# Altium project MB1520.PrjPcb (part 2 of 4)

## Sheet Arduino_Connector.SchDoc: Arduino Connector
size A4; Date: Not used; ApprovedBy: Not used; CheckedBy: Not used; Author: Not used; CompanyName: STMicroelectronics; DrawnBy: Not used; Engineer: Not used; Organization: Not used; Address1: Not used; Address2: Not used; Address3: Not used; Address4: Not used; DocumentNumber: Not used; Revision: Not used; SheetNumber: 16; SheetTotal: 19
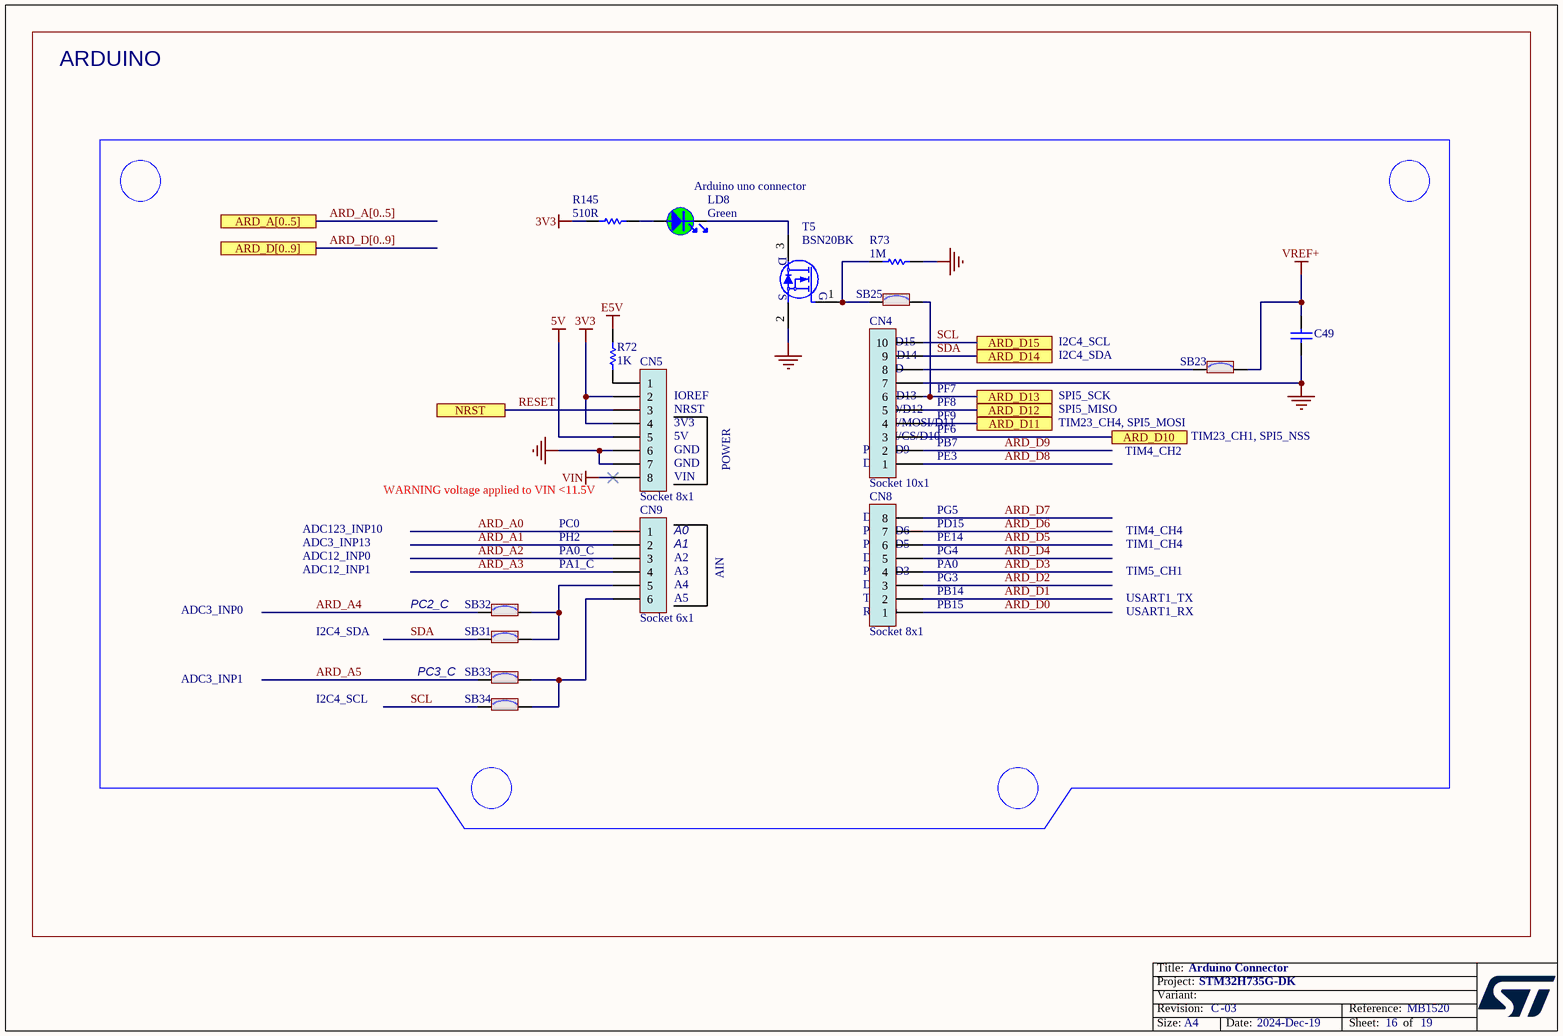
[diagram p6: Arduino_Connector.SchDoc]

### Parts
C49  Capacitor  [C0603]  (value not drawn)
CN4  Socket 10x1  [CON_SAMTEC_SSW-110-22-X-S-VS]
CN5  Socket 8x1  [CON_SAMTEC_SSW-108-22-X-S-VS]
CN8  Socket 8x1  [CON_SAMTEC_SSW-108-22-X-S-VS]
CN9  Socket 6x1  [CON_SAMTEC_SSW-106-22-X-S-VS]
LD8  value Green  [LED_0603_GREEN]  (hidden comment: LED_green)
R72  value 1K  [R0603]  (hidden comment: Resistor)
R73  value 1M  [R0603]  (hidden comment: Resistor)
R145  value 510R  [R0603]  (hidden comment: Resistor)
SB23  SB_ON  [SOLDER-BRIDGE_R0603-0R]  (value not drawn)
SB25  SB_ON  [SOLDER-BRIDGE_R0603-0R]  (value not drawn)
SB31  SB_ON  [SOLDER-BRIDGE_R0603-0R]  (value not drawn)
SB32  SB_ON  [SOLDER-BRIDGE_R0603-0R]  (value not drawn)
SB33  SB_ON  [SOLDER-BRIDGE_R0603-0R]  (value not drawn)
SB34  SB_ON  [SOLDER-BRIDGE_R0603-0R]  (value not drawn)
T5  value BSN20BK  [MOS_SOT23]  (hidden comment: BSN20)

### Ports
ARD_A[0..5], ARD_D10, ARD_D11, ARD_D12, ARD_D13, ARD_D14, ARD_D15, ARD_D[0..9], NRST

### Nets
3V3: CN5.2 CN5.4 R145.2
5V: CN5.5
E5V: R72.1
GND: C49.1 CN4.7 CN5.6 CN5.7 R73.2 T5.2(S)  [project net POE7]
VIN: CN5.8
VREF+: C49.2 SB23.2
ARD_A0: CN9.1
ARD_A1: CN9.2
ARD_A2: CN9.3
ARD_A3: CN9.4
ARD_A4: SB32.1
ARD_A5: SB33.1
ARD_D0: CN8.1
ARD_D1: CN8.2
ARD_D2: CN8.3
ARD_D3: CN8.4
ARD_D4: CN8.5
ARD_D5: CN8.6
ARD_D6: CN8.7
ARD_D7: CN8.8
ARD_D8: CN4.1
ARD_D9: CN4.2
ARD_D10: CN4.3 ; port ARD_D10
ARD_D11: CN4.4 ; port ARD_D11
ARD_D12: CN4.5 ; port ARD_D12
ARD_D13: CN4.6 SB25.2 ; port ARD_D13
RESET: CN5.3 ; port NRST
SCL: CN4.10 SB34.1 ; port ARD_D15
SDA: CN4.9 SB31.1 ; port ARD_D14
NetCN4_8: CN4.8 SB23.1
NetCN5_1: CN5.1 R72.2
NetCN9_5: CN9.5 SB31.2 SB32.2
NetCN9_6: CN9.6 SB33.2 SB34.2
NetLD8_1: LD8.1 R145.1
NetLD8_2: LD8.2 T5.3(D)
NetR73_1: R73.1 SB25.1 T5.1(G)

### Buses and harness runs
bus ARD_A[0..5] = port ARD_A[0..5]
bus ARD_D[0..9] = port ARD_D[0..9]

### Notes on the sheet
- ARDUINO
- (near LD8) Arduino uno connector
- (near CN4) SDA/D14
- SCL/D15
- (near CN4) AVDD
- (near CN4) GND
- I2C4_SCL
- I2C4_SDA
- (near CN5) IOREF
- (near CN5) NRST
- (near CN5) 3V3
- (near CN5) 5V
- (near CN4) PWM/CS/D10
- (near CN4) SCK/D13
- (near CN4) MISO/D12
- (near CN4) PWM/MOSI/D11
- (near CN4) PF6
- (near CN4) PB7
- (near CN4) PF9
- (near CN4) PF8
- (near CN4) PF7
- TIM23_CH4, SPI5_MOSI
- SPI5_MISO
- SPI5_SCK
- TIM23_CH1, SPI5_NSS
- WARNING voltage applied to VIN <11.5V
- (near CN5) GND
- (near CN5) VIN
- POWER
- (near CN8) D7
- (near CN4) D8
- (near CN4) PWM/D9
- PG5
- (near CN4) PE3
- TIM4_CH2
- ADC12_INP1
- ADC12_INP0
- ADC3_INP13
- ADC123_INP10
- PC0
- PH2
- PA0_C
- PA1_C
- (near CN9) A0
- (near CN9) A1
- (near CN9) A2
- (near CN9) A3
- AIN
- (near CN8) D4
- (near CN8) PWM/D3
- (near CN8) PWM/D5
- (near CN8) PWM/D6
- (near CN8) PG3
- (near CN8) PG4
- (near CN8) PE14
- (near CN8) PD15
- (near CN8) PA0
- TIM1_CH4
- TIM5_CH1
- TIM4_CH4
- ADC3_INP0
- PC2_C
- (near CN9) A4
- (near CN9) A5
- (near CN8) RX/D0
- (near CN8) TX/D1
- (near CN8) D2
- (near CN8) PB14
- (near CN8) PB15
- USART1_RX
- USART1_TX
- ADC3_INP1
- PC3_C

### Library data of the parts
C49 = MCD-00211: Capacitor, MLCC, 100nF, 16V, X7R, 10%, 0603, T=0,8mm; Manufacturer_Part_Number: CC0603KRX7R7BB104; Manufacturer: YAGEO; Part_Preference: Recommended; Provided_By: SUBCO; Component_Country_Of_Origin: China; ID: 2659; Order_Code_RS: 669-8763; ShowFields: YES
CN4 = MCD-00301: Socket, 10x1, 2.54mm, VR, SMT, Height 9.78mm; Manufacturer_Part_Number: SSW-110-22-L-S-VS; Manufacturer: SAMTEC; Part_Type: Connector; Part_Preference: Recommended; Provided_By: SUBCO; Component_Country_Of_Origin: China, Costa Rica, Malaysia, United States, Vietnam; ID: 2566; ShowFields: YES
CN5 = MCD-00300: Socket, 8x1, 2.54mm, VR, SMT, Height 9.78mm; Manufacturer_Part_Number: SSW-108-22-L-S-VS; Manufacturer: SAMTEC; Part_Type: Connector; Part_Preference: Recommended; Provided_By: SUBCO; Component_Country_Of_Origin: China, Costa Rica, Malaysia, United States, Vietnam; ID: 2571; ShowFields: YES
CN8 = MCD-00300: Socket, 8x1, 2.54mm, VR, SMT, Height 9.78mm; Part_Type: Connector; Manufacturer_Part_Number: SSW-108-22-L-S-VS; Manufacturer: SAMTEC; Part_Preference: Recommended; Provided_By: SUBCO; Component_Country_Of_Origin: China, Costa Rica, Malaysia, United States, Vietnam; ID: 2571; ShowFields: YES
CN9 = MCD-00299: Socket, 6x1, 2.54mm, VR, SMT, Height 9.78mm; Part_Type: Connector; Manufacturer_Part_Number: SSW-106-22-L-S-VS; Manufacturer: SAMTEC; Part_Preference: Recommended; Provided_By: SUBCO; Component_Country_Of_Origin: China, Costa Rica, Malaysia, United States, Vietnam; ID: 2569; ShowFields: YES
LD8 = MCD-02900: LED, Green, 2V, 20mA, 0603; Part_Type: Display; Manufacturer_Part_Number: 19-213SYGC/S530-E2/5T; Manufacturer: EVERLIGHT; Full_Alternate_Internal_Part_Number: MCD-00320; Part_Preference: Recommended; Partial_Alternate_Internal_Part_Number: MCD-00050; Component_Country_Of_Origin: China; ID: 5016; ShowFields: YES
R72 = MCD-00070: Resistor,1K,0603,1%,1/10W; Manufacturer_Part_Number: RC0603FR-071KL; Manufacturer: YAGEO; Part_Preference: Recommended; Provided_By: SUBCO; Component_Country_Of_Origin: China; ID: 2522; ShowFields: YES
R73 = MCD-00257: Resistor,1M,0603,1%,1/10W; Manufacturer_Part_Number: RC0603FR-071ML; Manufacturer: YAGEO; Part_Preference: Recommended; Provided_By: SUBCO; Component_Country_Of_Origin: China; ID: 2612; ShowFields: YES
R145 = MCD-00225: Resistor,510R,0603,1%,1/10W; Manufacturer_Part_Number: RC0603FR-07510RL; Manufacturer: YAGEO; Part_Preference: Recommended; Provided_By: SUBCO; Component_Country_Of_Origin: China; ID: 2644; ShowFields: YES
SB23 SB25 SB31-SB34 = MCD-00071: Solder Bridge ON; Part_Type: Misc; Manufacturer_Part_Number: RC0603JR-070RL; Manufacturer: YAGEO; Part_Preference: Recommended; Provided_By: SUBCO; ID: 2521; ShowFields: YES
T5 = MCD-01969: Transistor, N-channel enhancement mode field-effect transistor; Manufacturer: NEXPERIA; Part_Preference: Recommended; ID: 4069; Order_Code_RS: 136-4845; ShowFields: YES; Component_Country_Of_Origin: China

## Sheet STMod+.SchDoc: STMod+
size A4; Date: Not used; ApprovedBy: Not used; CheckedBy: Not used; Author: Not used; CompanyName: STMicroelectronics; DrawnBy: Not used; Engineer: Not used; Organization: Not used; Address1: Not used; Address2: Not used; Address3: Not used; Address4: Not used; DocumentNumber: Not used; Revision: Not used; SheetNumber: 14; SheetTotal: 19
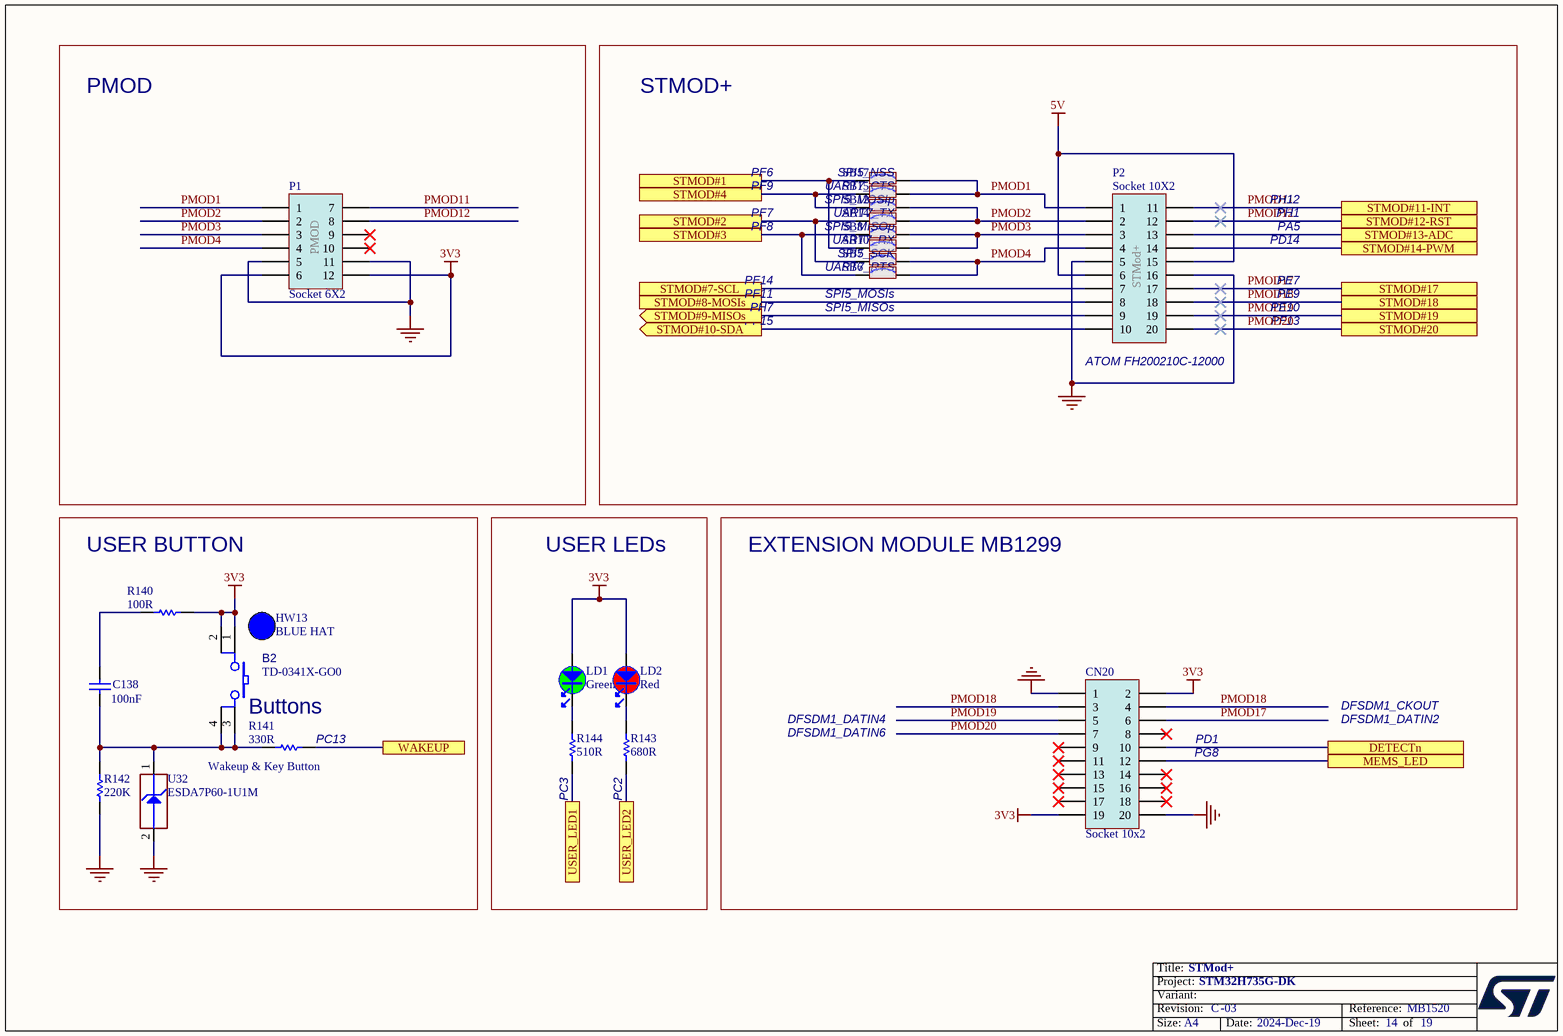
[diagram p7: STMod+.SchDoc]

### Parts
B2  Manufacturer_Part_Number: TD-0341X-GO0  [SWI_WEALTHMETAL_TD-0341_4P_BLUE]  (hidden comment: SW-PUSH-CMS)
C138  value 100nF  [C0402]  (hidden comment: Capacitor)
CN20  Socket 10x2  [CON_FCI_20021311-XXX20XXLF]
HW13  value BLUE HAT  (hidden comment: BUTTON_HAT_BLUE)  (mechanical)
LD1  value Green  [LED_0603_GREEN]  (hidden comment: LED_green)
LD2  value Red  [LED_0603_RED]  (hidden comment: LED_red)
P1  value Socket 6X2  [CON_SAMTEC_SSW-106-02-F-D-RA__PMOD]  (hidden comment: Socket 6X2 PMOD)
P2  value Socket 10X2  [CON_SAMTEC_SQT-110-01-F-D-RA__STMOD+]  (hidden comment: Socket 10X2 STMod+)
R140  value 100R  [R0402]  (hidden comment: Resistor)
R141  value 330R  [R0402]  (hidden comment: Resistor)
R142  value 220K  [R0402]  (hidden comment: Resistor)
R143  value 680R  [R0603]  (hidden comment: Resistor)
R144  value 510R  [R0603]  (hidden comment: Resistor)
SB6  SB_ON  [SOLDER-BRIDGE_R0603-0R]  (value not drawn)
SB7  SB_ON  [SOLDER-BRIDGE_R0603-0R]  (value not drawn)
SB8  SB_ON  [SOLDER-BRIDGE_R0603-0R]  (value not drawn)
SB10  SB_ON  [SOLDER-BRIDGE_R0603-0R]  (value not drawn)
SB12  SB_ON  [SOLDER-BRIDGE_R0603-0R]  (value not drawn)
SB14  SB_ON  [SOLDER-BRIDGE_R0603-0R]  (value not drawn)
SB15  SB_ON  [SOLDER-BRIDGE_R0603-0R]  (value not drawn)
SB17  SB_ON  [SOLDER-BRIDGE_R0603-0R]  (value not drawn)
U32  value ESDA7P60-1U1M  [ESD_QFN2_1P6X1_P125]  (hidden comment: ESD-TRANSIL)

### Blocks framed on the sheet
PMOD: P1
STMOD+: P2 SB6-SB8 SB10 SB12 SB14 SB15 SB17
USER LEDs: LD1 LD2 R143 R144
EXTENSION MODULE MB1299: CN20

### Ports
DETECTn, MEMS_LED, STMOD#1, STMOD#2, STMOD#3, STMOD#4, STMOD#7-SCL, STMOD#8-MOSIs, STMOD#9-MISOs (out), STMOD#10-SDA (out), STMOD#11-INT, STMOD#12-RST, STMOD#13-ADC, STMOD#14-PWM, STMOD#17, STMOD#18, STMOD#19, STMOD#20, USER_LED1, USER_LED2, WAKEUP

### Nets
3V3: B2.1 B2.2 CN20.2 CN20.19 LD1.1 LD2.1 P1.6 P1.12 R140.2
5V: P2.6 P2.15
GND: CN20.1 CN20.20 P1.5 P1.11 P2.5 P2.16 R142.1 U32.2(GND)  [project net POE7]
DETECTn: CN20.10 ; port DETECTn
MEMS_LED: CN20.12 ; port MEMS_LED
PF6: SB10.1 SB17.1 ; port STMOD#1
PF7: SB7.1 SB14.1 ; port STMOD#2
PMOD1: P1.1 P2.1 SB15.2 SB17.2
PMOD2: P1.2 P2.2 SB12.2 SB14.2
PMOD3: P1.3 P2.3 SB8.2 SB10.2
PMOD4: P1.4 P2.4 SB6.2 SB7.2
PMOD11: P1.7 P2.11 ; port STMOD#11-INT
PMOD12: P1.8 P2.12 ; port STMOD#12-RST
PMOD17: CN20.6 P2.17 ; port STMOD#17
PMOD18: CN20.3 CN20.4 P2.18 ; port STMOD#18
PMOD19: CN20.5 P2.19 ; port STMOD#19
PMOD20: CN20.7 P2.20 ; port STMOD#20
STMOD#3: SB6.1 SB8.1 ; port STMOD#3
STMOD#4: SB12.1 SB15.1 ; port STMOD#4
STMOD#7-SCL: P2.7 ; port STMOD#7-SCL
STMOD#8-MOSIs: P2.8 ; port STMOD#8-MOSIs
STMOD#9-MISOs: P2.9 ; port STMOD#9-MISOs
STMOD#10-SDA: P2.10 ; port STMOD#10-SDA
STMOD#13-ADC: P2.13 ; port STMOD#13-ADC
STMOD#14-PWM: P2.14 ; port STMOD#14-PWM
USER_LED1: R144.1 ; port USER_LED1
USER_LED2: R143.1 ; port USER_LED2
WAKEUP: R141.2 ; port WAKEUP
NetB2_3: B2.3 B2.4 C138.2 R141.1 R142.2 U32.1(IO1)
NetC138_1: C138.1 R140.1
NetLD1_2: LD1.2 R144.2
NetLD2_2: LD2.2 R143.2

Not connected (* = marked no-connect by the designer): CN20 8* 9* 11* 13* 14* 15* 16* 17* 18*; P1 9* 10*

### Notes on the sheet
- PF6
- (near SB17) SPI5_NSS
- PF9
- PF7
- PF8
- UART7_CTS
- SPI5_MOSIp
- UART7_TX
- SPI5_MISOp
- UART7_RX
- PH1
- PA5
- PH12
- PD14
- PF14
- PF11
- PH7
- SPI5_SCK
- UART7_RTS
- (near SB6) SPI5_MOSIs
- SPI5_MISOs
- PE7
- PE9
- PE10
- PF15
- (near P2) ATOM FH200210C-12000
- PF13
- USER BUTTON
- (near B2) Buttons
- DFSDM1_CKOUT
- (near R141) Wakeup & Key Button
- (near R141) PC13
- DFSDM1_DATIN4
- DFSDM1_DATIN6
- PD1
- PG8
- DFSDM1_DATIN2
- (near R144) PC3
- (near R143) PC2

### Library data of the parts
B2 = MCD-00002: Non-Open Push-Button 0.1A 24V; Part_Type: Misc; Manufacturer: WEALTHMETAL; Part_Preference: Not recommended; Partial_Alternate_Internal_Part_Number: MCD-03589; Value: SWITCH; Provided_By: SUBCO; Alternate_EMS: A; Component_Country_Of_Origin: Unknown; ID: 2464; ShowFields: YES
C138 = MCD-00006: Capacitor, MLCC, 100nF, 16V, X7R, +/-10%, 0402, T=0.5mm; Manufacturer_Part_Number: CC0402KRX7R7BB104; Manufacturer: YAGEO; Part_Preference: Recommended; Partial_Alternate_Internal_Part_Number: MCD-03299; Component_Country_Of_Origin: China; ID: 2474; Order_Code_RS: 616-9701; ShowFields: YES
CN20 = MCD-00147: Socket for MB1299, 10x2, 1.27mm, VR, TH, Height 4.30mm/2.40mm; Part_Type: Connector; Manufacturer_Part_Number: 20021311-00020T4LF; Manufacturer: AMPHENOL ICC; Alternate_Manufacturer_Part_Number: 234220S1410; Alternate_Manufacturer: JIUBABA; Part_Preference: Recommended; Provided_By: SUBCO; Component_Country_Of_Origin: China; ID: 2719; Order_Code_RS: 170-8859; ShowFields: YES
HW13 = MCD-00634: Blue Hat for switch TD0341X-G01-BLU; Part_Type: Misc; Manufacturer_Part_Number: 988.16.09.3.00002_SH-517; Manufacturer: JIUBABA; Part_Preference: Alternate; Provided_By: SUBCO; Alternate_EMS: A; Component_Country_Of_Origin: Unknown; ID: 3112; ShowFields: YES
LD1 = MCD-02900: as LD8 on sheet Arduino_Connector
LD2 = MCD-02899: LED, Red, 2V35, 20mA, 0603; Manufacturer_Part_Number: 19-213/R6C-AP1Q2B/5T; Manufacturer: EVERLIGHT; Part_Type: Display; Full_Alternate_Internal_Part_Number: MCD-00049; Part_Preference: Recommended; Component_Country_Of_Origin: China; ID: 5015; ShowFields: YES
P1 = MCD-00308: Socket, 6x2, 2.54mm, TH, RA, Height 8.51mm/7.62mm; Part_Type: Connector; Manufacturer_Part_Number: SSW-106-02-F-D-RA; Manufacturer: SAMTEC; Part_Preference: Recommended; Provided_By: SUBCO; Component_Country_Of_Origin: China, Costa Rica, Malaysia, United States, Vietnam; ID: 2562; Order_Code_RS: 207-9142; ShowFields: YES
P2 = MCD-00309: Socket 10x2, 2.00mm, RA, TH, Height 6.35mm/2.29mm; Part_Type: Connector; Manufacturer_Part_Number: SQT-110-01-F-D-RA; Manufacturer: SAMTEC; Alternate_Manufacturer_Part_Number: FH200020C-12300; Alternate_Manufacturer: JIUBABA; Part_Preference: Recommended; Provided_By: SUBCO; Component_Country_Of_Origin: China, Costa Rica, Malaysia, United States, Vietnam; ID: 2557; Order_Code_RS: 180-1541; ShowFields: YES
R140 = MCD-00067: Resistor, 100R, 0402, +/- 1%, 1/16W; Manufacturer_Part_Number: RC0402FR-07100RL; Manufacturer: YAGEO; Part_Preference: Recommended; Component_Country_Of_Origin: China; ID: 2527; ShowFields: YES
R141 = MCD-00062: Resistor,330R,0402,1%,1/16W; Manufacturer_Part_Number: RC0402FR-07330RL; Manufacturer: YAGEO; Part_Preference: Recommended; Provided_By: SUBCO; Component_Country_Of_Origin: China; ID: 2529; ShowFields: YES
R142 = MCD-00164: Resistor,220K,0402,1%,1/16W; Manufacturer_Part_Number: RC0402FR-07220KL; Manufacturer: YAGEO; Part_Preference: Recommended; Provided_By: SUBCO; Component_Country_Of_Origin: China; ID: 2704; ShowFields: YES
R143 = MCD-00508: Resistor,680R,0603,1%,1/10W; Manufacturer_Part_Number: RC0603FR-07680RL; Manufacturer: YAGEO; Part_Preference: Recommended; ECCN_US: EAR99; ECCN_EU: NEC; Provided_By: SUBCO; Component_Country_Of_Origin: China; ID: 3235; ShowFields: YES
R144 = MCD-00225: as R145 on sheet Arduino_Connector
SB6-SB8 SB10 SB12 SB14 SB15 SB17 = MCD-00071: as SB23 on sheet Arduino_Connector
U32 = MCD-00251: High power transient voltage suppressor, 7V breakdown; Part_Type: Diode; Manufacturer: STMICROELECTRONICS; BMS_Part_Number: 9179042; Manufacturer_HQ_COO: EU; Part_Preference: Recommended; Provided_By: SUBCO with ST control; Component_Country_Of_Origin: China; ID: 2618; ShowFields: YES

## Sheet STM32_microcontroller_IOs.SchDoc: STM32 microcontroller IOs
size A3; Date: Not used; ApprovedBy: Not used; CheckedBy: Not used; Author: Not used; CompanyName: STMicroelectronics; DrawnBy: Not used; Engineer: Not used; Organization: Not used; Address1: Not used; Address2: Not used; Address3: Not used; Address4: Not used; DocumentNumber: Not used; Revision: Not used; SheetNumber: 3; SheetTotal: 19
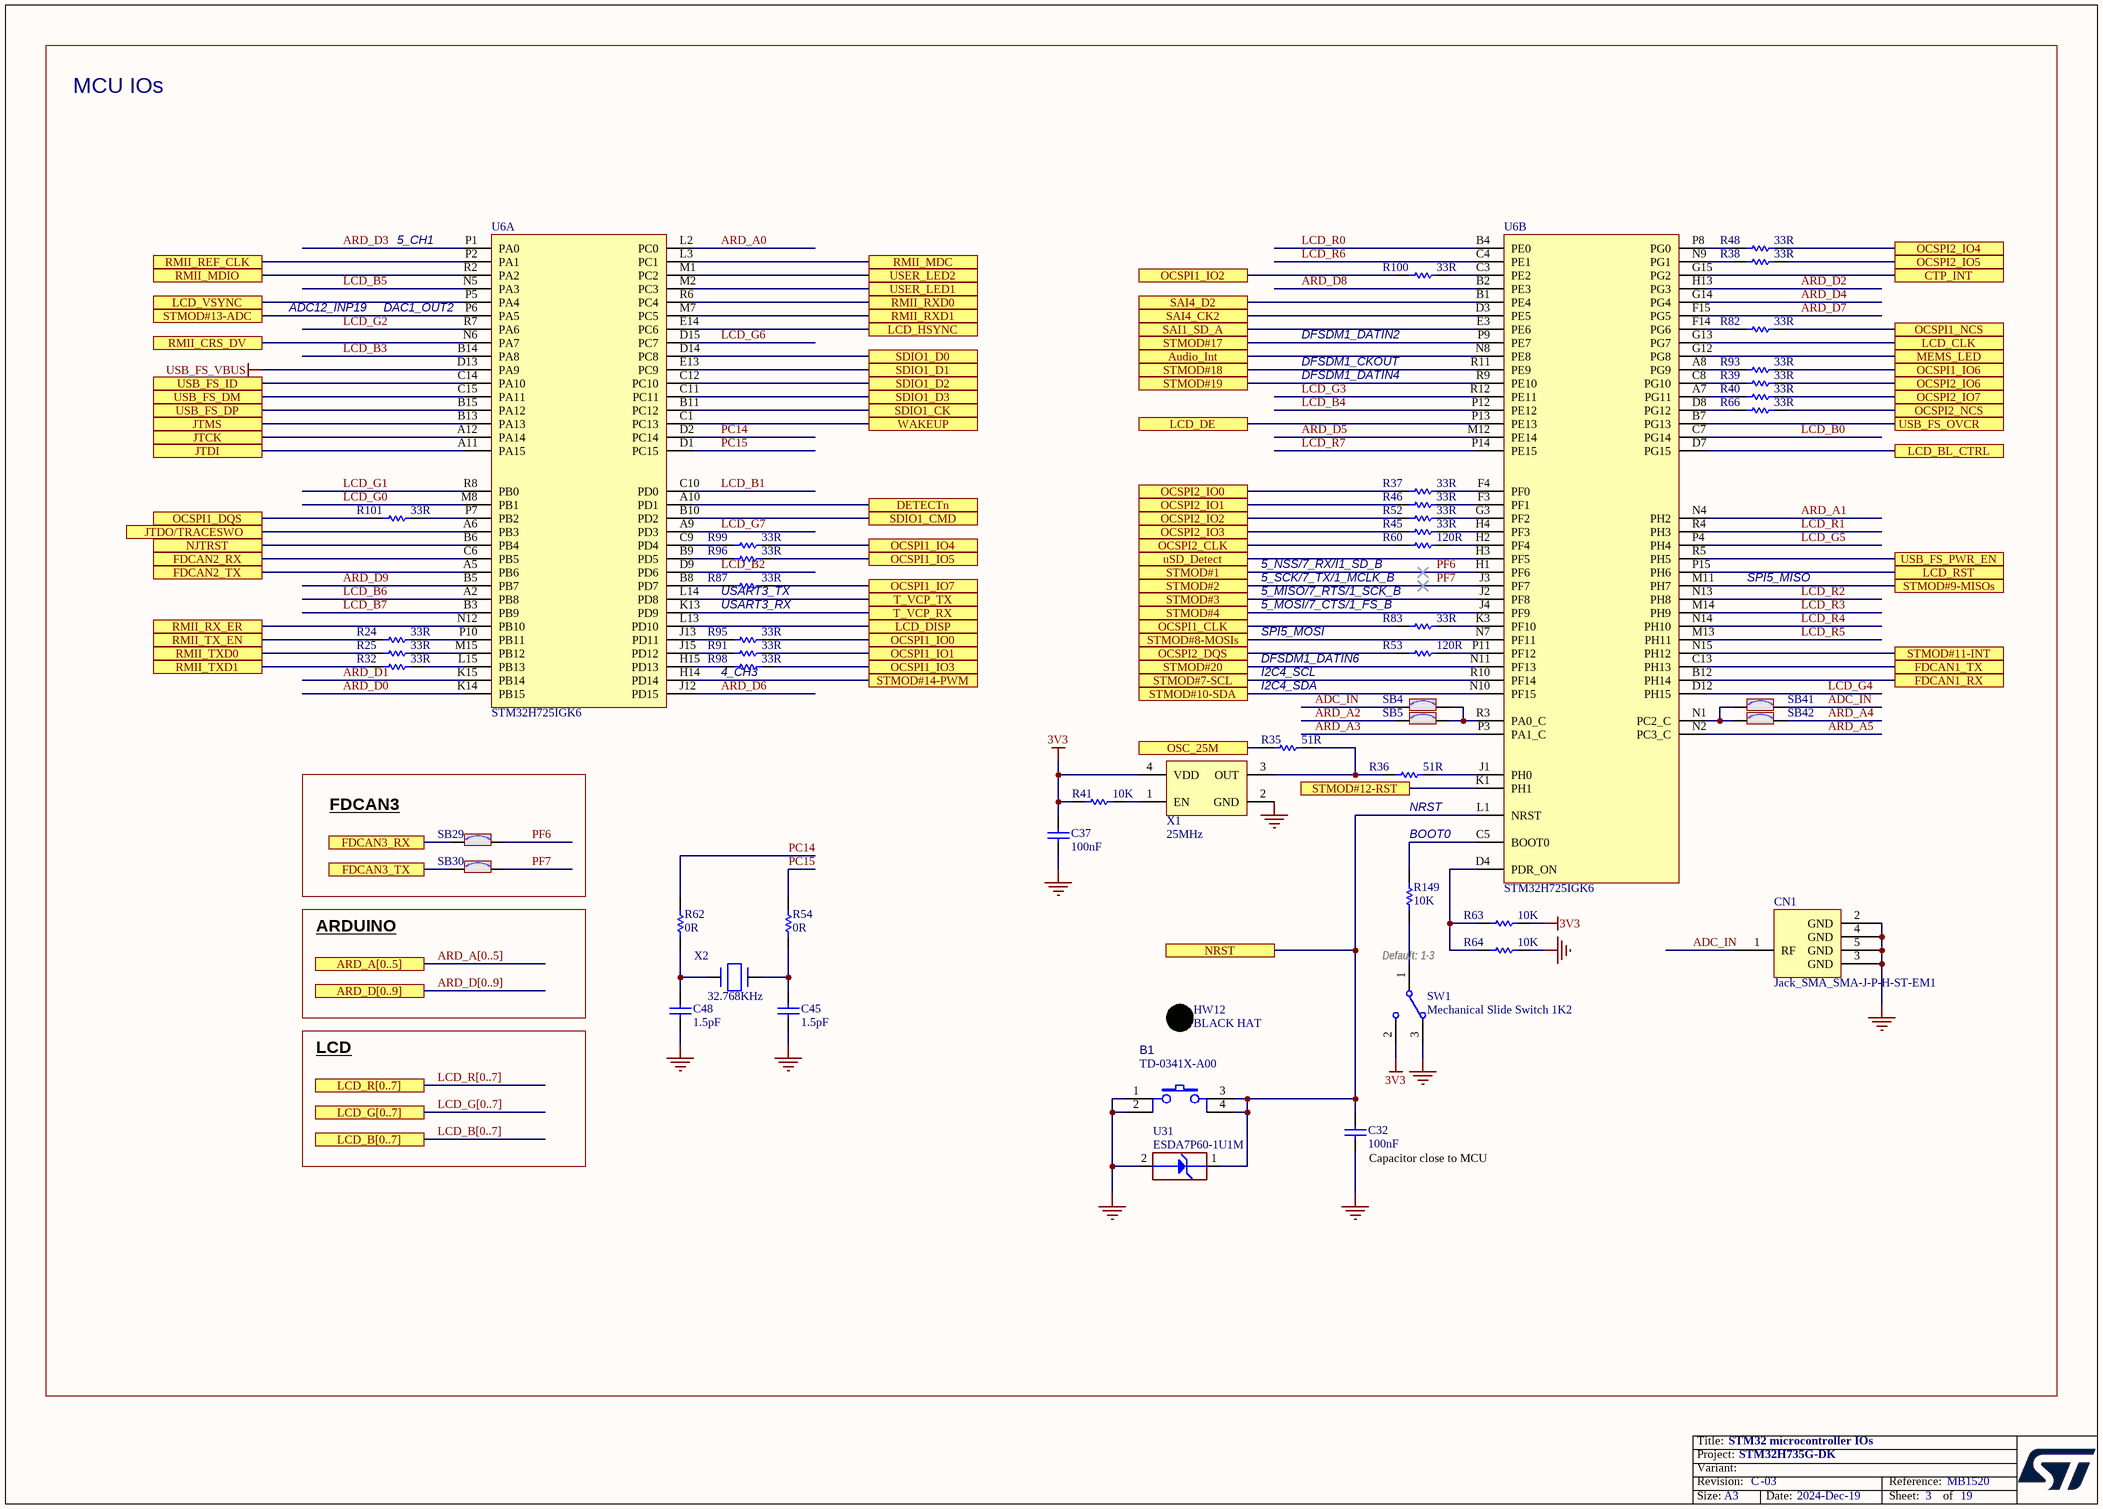
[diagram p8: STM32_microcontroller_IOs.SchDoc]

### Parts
B1  Manufacturer_Part_Number: TD-0341X-A00  [SWI_WEALTHMETAL_TD-0341_4P_BLACK]  (hidden comment: SW-PUSH-CMS)
C32  value 100nF  [C0402]  (hidden comment: Capacitor)
C37  value 100nF  [C0402]  (hidden comment: Capacitor)
C45  value 1.5pF  [C0402]  (hidden comment: Capacitor)
C48  value 1.5pF  [C0402]  (hidden comment: Capacitor)
CN1  value Jack_SMA_SMA-J-P-H-ST-EM1  [CON_SAMTEC_SMA-J-P-X-ST-EM1]  (hidden comment: SMA-J-P-H-ST-EM1)
HW12  value BLACK HAT  (hidden comment: BUTTON_HAT_BLACK)  (mechanical)
R24  value 33R  [R0402]  (hidden comment: Resistor)
R25  value 33R  [R0402]  (hidden comment: Resistor)
R32  value 33R  [R0402]  (hidden comment: Resistor)
R35  value 51R  [R0402]  (hidden comment: Resistor)
R36  value 51R  [R0402]  (hidden comment: Resistor)
R37  value 33R  [R0402]  (hidden comment: Resistor)
R38  value 33R  [R0402]  (hidden comment: Resistor)
R39  value 33R  [R0402]  (hidden comment: Resistor)
R40  value 33R  [R0402]  (hidden comment: Resistor)
R41  value 10K  [R0402]  (hidden comment: Resistor)
R45  value 33R  [R0402]  (hidden comment: Resistor)
R46  value 33R  [R0402]  (hidden comment: Resistor)
R48  value 33R  [R0402]  (hidden comment: Resistor)
R52  value 33R  [R0402]  (hidden comment: Resistor)
R53  value 120R  [R0402]  (hidden comment: Resistor)
R54  value 0R  [R0603]  (hidden comment: Resistor)
R60  value 120R  [R0402]  (hidden comment: Resistor)
R62  value 0R  [R0603]  (hidden comment: Resistor)
R63  value 10K  [R0402]  (hidden comment: Resistor)
R64  value 10K  [R0402]  (hidden comment: Resistor)
R66  value 33R  [R0402]  (hidden comment: Resistor)
R82  value 33R  [R0402]  (hidden comment: Resistor)
R83  value 33R  [R0402]  (hidden comment: Resistor)
R87  value 33R  [R0402]  (hidden comment: Resistor)
R91  value 33R  [R0402]  (hidden comment: Resistor)
R93  value 33R  [R0402]  (hidden comment: Resistor)
R95  value 33R  [R0402]  (hidden comment: Resistor)
R96  value 33R  [R0402]  (hidden comment: Resistor)
R98  value 33R  [R0402]  (hidden comment: Resistor)
R99  value 33R  [R0402]  (hidden comment: Resistor)
R100  value 33R  [R0402]  (hidden comment: Resistor)
R101  value 33R  [R0402]  (hidden comment: Resistor)
R149  value 10K  [R0402]  (hidden comment: Resistor)
SB4  SB_ON  [SOLDER-BRIDGE_R0603-0R]  (value not drawn)
SB5  SB_ON  [SOLDER-BRIDGE_R0603-0R]  (value not drawn)
SB29  SB_ON  [SOLDER-BRIDGE_R0603-0R]  (value not drawn)
SB30  SB_ON  [SOLDER-BRIDGE_R0603-0R]  (value not drawn)
SB41  SB_ON  [SOLDER-BRIDGE_R0603-0R]  (value not drawn)
SB42  SB_ON  [SOLDER-BRIDGE_R0603-0R]  (value not drawn)
SW1  value Mechanical Slide Switch 1K2  [SWI_EAO_09-03290-01_EXTENDED_STRAIGHT_BLACK]  (hidden comment: SW_MECA_1K2)
U6  value STM32H725IGK6  [ICC_UFBGA201_176+25_10X10_P065]  (hidden comment: STM32H725IGK6U)  (parts A,B of 3)
U31  value ESDA7P60-1U1M  [ESD_QFN2_1P6X1_P125]  (hidden comment: ESD-TRANSIL)
X1  value 25MHz  [OSC_NDK_NZ2520SB_4P]  (hidden comment: OSCILLATOR_4_PINS)
X2  value 32.768KHz  [CRY_NX3215SA_2P]  (hidden comment: XTAL_2_PINS)

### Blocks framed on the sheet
FDCAN3: SB29 SB30

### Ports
ARD_A[0..5], ARD_D[0..9], Audio_Int, CTP_INT, DETECTn, FDCAN1_RX, FDCAN1_TX, FDCAN2_RX, FDCAN2_TX, FDCAN3_RX, FDCAN3_TX, JTCK, JTDI, JTDO/TRACESWO, JTMS, LCD_B[0..7], LCD_BL_CTRL, LCD_CLK, LCD_DE, LCD_DISP, LCD_G[0..7], LCD_HSYNC, LCD_R[0..7], LCD_RST, LCD_VSYNC, MEMS_LED, NJTRST, NRST, OCSPI1_CLK, OCSPI1_DQS, OCSPI1_IO0, OCSPI1_IO1, OCSPI1_IO2, OCSPI1_IO3, OCSPI1_IO4, OCSPI1_IO5, OCSPI1_IO6, OCSPI1_IO7, OCSPI1_NCS, OCSPI2_CLK, OCSPI2_DQS, OCSPI2_IO0, OCSPI2_IO1, OCSPI2_IO2, OCSPI2_IO3, OCSPI2_IO4, OCSPI2_IO5, OCSPI2_IO6, OCSPI2_IO7, OCSPI2_NCS, OSC_25M, RMII_CRS_DV, RMII_MDC, RMII_MDIO, RMII_REF_CLK, RMII_RX_ER, RMII_RXD0, RMII_RXD1, RMII_TX_EN, RMII_TXD0, RMII_TXD1, SAI1_SD_A, SAI4_CK2, SAI4_D2, SDIO1_CK, SDIO1_CMD, SDIO1_D0, SDIO1_D1, SDIO1_D2, SDIO1_D3, STMOD#1, STMOD#2, STMOD#3, STMOD#4, STMOD#7-SCL, STMOD#8-MOSIs, STMOD#9-MISOs, STMOD#10-SDA, STMOD#11-INT, STMOD#12-RST, STMOD#13-ADC, STMOD#14-PWM, STMOD#17, STMOD#18, STMOD#19, STMOD#20, T_VCP_RX, T_VCP_TX, USB_FS_DM, USB_FS_DP, USB_FS_ID, USB_FS_OVCR, USB_FS_PWR_EN, uSD_Detect, USER_LED1, USER_LED2, WAKEUP

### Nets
3V3: C37.2 R41.2 R63.1 SW1.2 X1.4(VDD)
GND: B1.1 B1.2 C32.1 C37.1 C45.1 C48.1 CN1.2(GND) CN1.3(GND) CN1.4(GND) CN1.5(GND) R64.1 SW1.3 U31.2(GND) X1.2(GND)  [project net POE7]
USB_FS_VBUS: U6.D13(PA9)
ADC_IN: CN1.1(RF) SB4.1 SB41.2
ARD_A0: U6.L2(PC0)
ARD_A1: U6.N4(PH2)
ARD_A2: SB5.1
ARD_A3: U6.P3(PA1_C)
ARD_A4: SB42.2
ARD_A5: U6.N2(PC3_C)
ARD_D0: U6.K14(PB15)
ARD_D1: U6.K15(PB14)
ARD_D2: U6.H13(PG3)
ARD_D3: U6.P1(PA0)
ARD_D4: U6.G14(PG4)
ARD_D5: U6.M12(PE14)
ARD_D6: U6.J12(PD15)
ARD_D7: U6.F15(PG5)
ARD_D8: U6.B2(PE3)
ARD_D9: U6.B5(PB7)
Audio_Int: U6.N8(PE8) ; port Audio_Int
CTP_INT: U6.G15(PG2) ; port CTP_INT
DETECTn: U6.A10(PD1) ; port DETECTn
FDCAN1_RX: U6.B12(PH14) ; port FDCAN1_RX
FDCAN1_TX: U6.C13(PH13) ; port FDCAN1_TX
FDCAN2_RX: U6.C6(PB5) ; port FDCAN2_RX
FDCAN2_TX: U6.A5(PB6) ; port FDCAN2_TX
FDCAN3_RX: SB29.1 ; port FDCAN3_RX
FDCAN3_TX: SB30.1 ; port FDCAN3_TX
LCD_B0: U6.C7(PG14)
LCD_B1: U6.C10(PD0)
LCD_B2: U6.D9(PD6)
LCD_B3: U6.B14(PA8)
LCD_B4: U6.P12(PE12)
LCD_B5: U6.N5(PA3)
LCD_B6: U6.A2(PB8)
LCD_B7: U6.B3(PB9)
LCD_BL_CTRL: U6.D7(PG15) ; port LCD_BL_CTRL
LCD_CLK: U6.G13(PG7) ; port LCD_CLK
LCD_DE: U6.P13(PE13) ; port LCD_DE
LCD_DISP: U6.L13(PD10) ; port LCD_DISP
LCD_G0: U6.M8(PB1)
LCD_G1: U6.R8(PB0)
LCD_G2: U6.R7(PA6)
LCD_G3: U6.R12(PE11)
LCD_G4: U6.D12(PH15)
LCD_G5: U6.P4(PH4)
LCD_G6: U6.D15(PC7)
LCD_G7: U6.A9(PD3)
LCD_HSYNC: U6.E14(PC6) ; port LCD_HSYNC
LCD_R0: U6.B4(PE0)
LCD_R1: U6.R4(PH3)
LCD_R2: U6.N13(PH8)
LCD_R3: U6.M14(PH9)
LCD_R4: U6.N14(PH10)
LCD_R5: U6.M13(PH11)
LCD_R6: U6.C4(PE1)
LCD_R7: U6.P14(PE15)
LCD_RST: U6.P15(PH6) ; port LCD_RST
LCD_VSYNC: U6.P5(PA4) ; port LCD_VSYNC
MEMS_LED: U6.G12(PG8) ; port MEMS_LED
NJTRST: U6.B6(PB4) ; port NJTRST
OCSPI1_CLK: R83.1 ; port OCSPI1_CLK
OCSPI1_DQS: R101.1 ; port OCSPI1_DQS
OCSPI1_IO0: R95.2 ; port OCSPI1_IO0
OCSPI1_IO1: R91.2 ; port OCSPI1_IO1
OCSPI1_IO2: R100.1 ; port OCSPI1_IO2
OCSPI1_IO3: R98.2 ; port OCSPI1_IO3
OCSPI1_IO4: R99.2 ; port OCSPI1_IO4
OCSPI1_IO5: R96.2 ; port OCSPI1_IO5
OCSPI1_IO6: R93.2 ; port OCSPI1_IO6
OCSPI1_IO7: R87.2 ; port OCSPI1_IO7
OCSPI1_NCS: R82.2 ; port OCSPI1_NCS
OCSPI2_CLK: R60.1 ; port OCSPI2_CLK
OCSPI2_DQS: R53.1 ; port OCSPI2_DQS
OCSPI2_IO0: R37.1 ; port OCSPI2_IO0
OCSPI2_IO1: R46.1 ; port OCSPI2_IO1
OCSPI2_IO2: R52.1 ; port OCSPI2_IO2
OCSPI2_IO3: R45.1 ; port OCSPI2_IO3
OCSPI2_IO4: R48.2 ; port OCSPI2_IO4
OCSPI2_IO5: R38.2 ; port OCSPI2_IO5
OCSPI2_IO6: R39.2 ; port OCSPI2_IO6
OCSPI2_IO7: R40.2 ; port OCSPI2_IO7
OCSPI2_NCS: R66.2 ; port OCSPI2_NCS
OSC_25M: R35.1 ; port OSC_25M
PC14: R62.1 U6.D2(PC14)
PC15: R54.1 U6.D1(PC15)
PF6: SB29.2 U6.H1(PF6) ; port STMOD#1
PF7: SB30.2 U6.J3(PF7) ; port STMOD#2
PMOD11: U6.N15(PH12) ; port STMOD#11-INT
PMOD12: U6.K1(PH1) ; port STMOD#12-RST
PMOD17: U6.P9(PE7) ; port STMOD#17
PMOD18: U6.R11(PE9) ; port STMOD#18
PMOD19: U6.R9(PE10) ; port STMOD#19
PMOD20: U6.N11(PF13) ; port STMOD#20
RESET: B1.3 B1.4 C32.2 U6.L1(NRST) U31.1(IO1) ; port NRST
RMII_CRS_DV: U6.N6(PA7) ; port RMII_CRS_DV
RMII_MDC: U6.L3(PC1) ; port RMII_MDC
RMII_MDIO: U6.R2(PA2) ; port RMII_MDIO
RMII_REF_CLK: U6.P2(PA1) ; port RMII_REF_CLK
RMII_RX_ER: U6.N12(PB10) ; port RMII_RX_ER
RMII_RXD0: U6.R6(PC4) ; port RMII_RXD0
RMII_RXD1: U6.M7(PC5) ; port RMII_RXD1
RMII_TX_EN: R24.1 ; port RMII_TX_EN
RMII_TXD0: R25.1 ; port RMII_TXD0
RMII_TXD1: R32.1 ; port RMII_TXD1
SAI1_SD_A: U6.E3(PE6) ; port SAI1_SD_A
SAI4_CK2: U6.D3(PE5) ; port SAI4_CK2
SAI4_D2: U6.B1(PE4) ; port SAI4_D2
SDIO1_CK: U6.B11(PC12) ; port SDIO1_CK
SDIO1_CMD: U6.B10(PD2) ; port SDIO1_CMD
SDIO1_D0: U6.D14(PC8) ; port SDIO1_D0
SDIO1_D1: U6.E13(PC9) ; port SDIO1_D1
SDIO1_D2: U6.C12(PC10) ; port SDIO1_D2
SDIO1_D3: U6.C11(PC11) ; port SDIO1_D3
STMOD#3: U6.J2(PF8) ; port STMOD#3
STMOD#4: U6.J4(PF9) ; port STMOD#4
STMOD#7-SCL: U6.R10(PF14) ; port STMOD#7-SCL
STMOD#8-MOSIs: U6.N7(PF11) ; port STMOD#8-MOSIs
STMOD#9-MISOs: U6.M11(PH7) ; port STMOD#9-MISOs
STMOD#10-SDA: U6.N10(PF15) ; port STMOD#10-SDA
STMOD#13-ADC: U6.P6(PA5) ; port STMOD#13-ADC
STMOD#14-PWM: U6.H14(PD14) ; port STMOD#14-PWM
T_JTDI: U6.A11(PA15) ; port JTDI
T_SWCLK: U6.A12(PA14) ; port JTCK
T_SWDIO: U6.B13(PA13) ; port JTMS
T_SWO: U6.A6(PB3) ; port JTDO/TRACESWO
T_VCP_RX: U6.K13(PD9) ; port T_VCP_RX
T_VCP_TX: U6.L14(PD8) ; port T_VCP_TX
USB_FS_DM: U6.C15(PA11) ; port USB_FS_DM
USB_FS_DP: U6.B15(PA12) ; port USB_FS_DP
USB_FS_ID: U6.C14(PA10) ; port USB_FS_ID
USB_FS_OVCR: U6.B7(PG13) ; port USB_FS_OVCR
USB_FS_PWR_EN: U6.R5(PH5) ; port USB_FS_PWR_EN
uSD_Detect: U6.H3(PF5) ; port uSD_Detect
USER_LED1: U6.M2(PC3) ; port USER_LED1
USER_LED2: U6.M1(PC2) ; port USER_LED2
WAKEUP: U6.C1(PC13) ; port WAKEUP
NetC45_2: C45.2 R54.2 X2.1(X1)
NetC48_2: C48.2 R62.2 X2.2(X2)
NetR24_2: R24.2 U6.P10(PB11)
NetR25_2: R25.2 U6.M15(PB12)
NetR32_2: R32.2 U6.L15(PB13)
NetR35_2: R35.2 R36.1 X1.3(OUT)
NetR36_2: R36.2 U6.J1(PH0)
NetR37_2: R37.2 U6.F4(PF0)
NetR38_1: R38.1 U6.N9(PG1)
NetR39_1: R39.1 U6.C8(PG10)
NetR40_1: R40.1 U6.A7(PG11)
NetR41_1: R41.1 X1.1(EN)
NetR45_2: R45.2 U6.H4(PF3)
NetR46_2: R46.2 U6.F3(PF1)
NetR48_1: R48.1 U6.P8(PG0)
NetR52_2: R52.2 U6.G3(PF2)
NetR53_2: R53.2 U6.P11(PF12)
NetR60_2: R60.2 U6.H2(PF4)
NetR63_2: R63.2 R64.2 U6.D4(PDR_ON)
NetR66_1: R66.1 U6.D8(PG12)
NetR82_1: R82.1 U6.F14(PG6)
NetR83_2: R83.2 U6.K3(PF10)
NetR87_1: R87.1 U6.B8(PD7)
NetR91_1: R91.1 U6.J15(PD12)
NetR93_1: R93.1 U6.A8(PG9)
NetR95_1: R95.1 U6.J13(PD11)
NetR96_1: R96.1 U6.B9(PD5)
NetR98_1: R98.1 U6.H15(PD13)
NetR99_1: R99.1 U6.C9(PD4)
NetR100_2: R100.2 U6.C3(PE2)
NetR101_2: R101.2 U6.P7(PB2)
NetR149_1: R149.1 U6.C5(BOOT0)
NetR149_2: R149.2 SW1.1
NetSB4_2: SB4.2 SB5.2 U6.R3(PA0_C)
NetSB41_1: SB41.1 SB42.1 U6.N1(PC2_C)

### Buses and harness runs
bus ARD_A[0..5] = port ARD_A[0..5]
bus ARD_D[0..9] = port ARD_D[0..9]
bus LCD_B[0..7] = port LCD_B[0..7]
bus LCD_G[0..7] = port LCD_G[0..7]
bus LCD_R[0..7] = port LCD_R[0..7]

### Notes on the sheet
- MCU IOs
- 5_CH1
- ADC12_INP19
- (near U6) DAC1_OUT2
- DFSDM1_DATIN2
- DFSDM1_CKOUT
- DFSDM1_DATIN4
- 5_NSS/7_RX/I1_SD_B
- 5_SCK/7_TX/1_MCLK_B
- SPI5_MISO
- (near R87) USART3_TX
- (near R87) USART3_RX
- 5_MISO/7_RTS/1_SCK_B
- 5_MOSI/7_CTS/1_FS_B
- SPI5_MOSI
- (near R98) 4_CH3
- DFSDM1_DATIN6
- I2C4_SDA
- I2C4_SCL
- BOOT0
- (near R36) NRST
- ARDUINO
- Default: 1-3
- LCD
- (near C32) Capacitor close to MCU

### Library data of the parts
B1 = MCD-00001: Non-Open Push-Button 0.1A 24V BLACK; Part_Type: Misc; Manufacturer: WEALTHMETAL; Part_Preference: Not recommended; Partial_Alternate_Internal_Part_Number: MCD-03587; Value: SWITCH; Provided_By: SUBCO; Alternate_EMS: A; Component_Country_Of_Origin: Unknown; ID: 2463; ShowFields: YES
C32 C37 = MCD-00006: Capacitor, MLCC, 100nF, 16V, X7R, +/-10%, 0402, T=0.5mm; Manufacturer_Part_Number: CC0402KRX7R7BB104; Manufacturer: YAGEO; Part_Preference: Recommended; Partial_Alternate_Internal_Part_Number: MCD-03299; Component_Country_Of_Origin: China; ID: 2474; Order_Code_RS: 9402047; ShowFields: YES
C45 C48 = MCD-00563: Capacitor, MLCC, 1.5pF, 50V, NPO, +-0.25pF, 0402, T=0,5mm; Manufacturer_Part_Number: CC0402CRNPO9BN1R5; Manufacturer: YAGEO; Part_Preference: Recommended; Provided_By: SUBCO; Component_Country_Of_Origin: China; ID: 3175; ShowFields: YES
CN1 = MCD-00279: RF SMA connector PCB edge; Manufacturer: SAMTEC; Part_Preference: Recommended; ECCN_US: EAR99; ECCN_EU: NEC; Provided_By: SUBCO; Component_Country_Of_Origin: China, Costa Rica, Malaysia, United States, Vietnam; ID: 2586; Order_Code_RS: 158-5721; ShowFields: YES
HW12 = MCD-00635: Black Hat for switch TD0341X-G01-BLA; Part_Type: Misc; Manufacturer_Part_Number: 988.16.09.3.00003_SH-517; Manufacturer: JIUBABA; Part_Preference: Alternate; Provided_By: SUBCO; Alternate_EMS: A; Component_Country_Of_Origin: Unknown; ID: 3106; ShowFields: YES
R24 R25 R32 R37-R40 R45 R46 R48 R52 R66 R82 R83 R87 R91 R93 R95 R96 R98-R101 = MCD-00455: Resistor,33R,0402,1%,1/16W; Manufacturer_Part_Number: RC0402FR-0733RL; Manufacturer: YAGEO; Part_Preference: Recommended; Provided_By: SUBCO; Component_Country_Of_Origin: China; ID: 2821; ShowFields: YES
R35 R36 = MCD-00485: Resistor,51R,0402,1%,1/16W; Manufacturer_Part_Number: RC0402FR-0751RL; Manufacturer: YAGEO; Part_Preference: Recommended; Provided_By: SUBCO; Component_Country_Of_Origin: China; ID: 2790; ShowFields: YES
R41 R63 R64 R149 = MCD-00053: Resistor,10K,0402,1%,1/16W; Manufacturer_Part_Number: RC0402FR-0710KL; Manufacturer: YAGEO; BMS_Part_Number: 9131590; Part_Preference: Recommended; Provided_By: SUBCO; Component_Country_Of_Origin: China; ID: 2539; ShowFields: YES
R53 R60 = MCD-00194: Resistor, 120R, 0402, +/-1%, 1/16W; Manufacturer_Part_Number: RC0402FR-07120RL; Manufacturer: YAGEO; Part_Preference: Recommended; Component_Country_Of_Origin: China; ID: 2674; ShowFields: YES
R54 R62 = MCD-00181: Resistor,0R,0603,ULO; Manufacturer_Part_Number: PMR03EZPJ000; Manufacturer: ROHM SEMICONDUCTOR; Part_Preference: Recommended; Provided_By: SUBCO; Component_Country_Of_Origin: Philippines, Thailand; ID: 2691; ShowFields: YES
SB4 SB5 SB29 SB30 SB41 SB42 = MCD-00071: as SB23 on sheet Arduino_Connector
SW1 = MCD-00566: Mechanical Slide Switches 1K2 BLK ACT GOLD STRT MNT; Part_Type: Misc; Manufacturer_Part_Number: 09.03290.01; Manufacturer: EAO; Part_Preference: Recommended; Provided_By: SUBCO; Component_Country_Of_Origin: Switzerland; ID: 3181; ShowFields: YES
U6 = MCD-01673: STM32H725IGK6 MCU, Cut1.0, 10x10x0.6mm, Pitch0.65mm, Int SMPS; Part_Type: IC; Manufacturer: STMICROELECTRONICS; Manufacturer_HQ_COO: EU; Part_Preference: Recommended; ECCN_US: 3A991A2; ECCN_EU: NEC; Provided_By: SUBCO with ST control; Component_Country_Of_Origin: Taiwan; ID: 3773; ShowFields: YES
U31 = MCD-00251: as U32 on sheet STMod+
X1 = MCD-00597: Oscillator 25Mhz, +-50ppm, Vcc:3.3V typ, square wave: [0.1Vcc;0.9Vcc], Enable pin, SMD; Part_Type: Crystal_Osc; Manufacturer_Part_Number: NZ2520SH-25MHZ-END4869C; Manufacturer: NDK; Alternate_Manufacturer_Part_Number: NZ2520SB 25MHz END4869B; BMS_Part_Number: 9157050; Part_Preference: Recommended; Provided_By: SUBCO; Component_Country_Of_Origin: Unknown; ID: 3148; ShowFields: YES
X2 = MCD-00091: Crystal 32.768kHz, 6pF, +-20ppm, 50Kohms max, SMD; Part_Type: Crystal_Osc; Manufacturer_Part_Number: NX3215SA-32.768KHZ-EXS00A-MU00525; Manufacturer: NDK; BMS_Part_Number: 9157034; Part_Preference: Recommended; Provided_By: SUBCO; Component_Country_Of_Origin: Unknown; ID: 2553; ShowFields: YES

## Sheet Ethernet.SchDoc: Ethernet
size A4; Date: Not used; ApprovedBy: Not used; CheckedBy: Not used; Author: Not used; CompanyName: STMicroelectronics; DrawnBy: Not used; Engineer: Not used; Organization: Not used; Address1: Not used; Address2: Not used; Address3: Not used; Address4: Not used; DocumentNumber: Not used; Revision: Not used; SheetNumber: 5; SheetTotal: 19
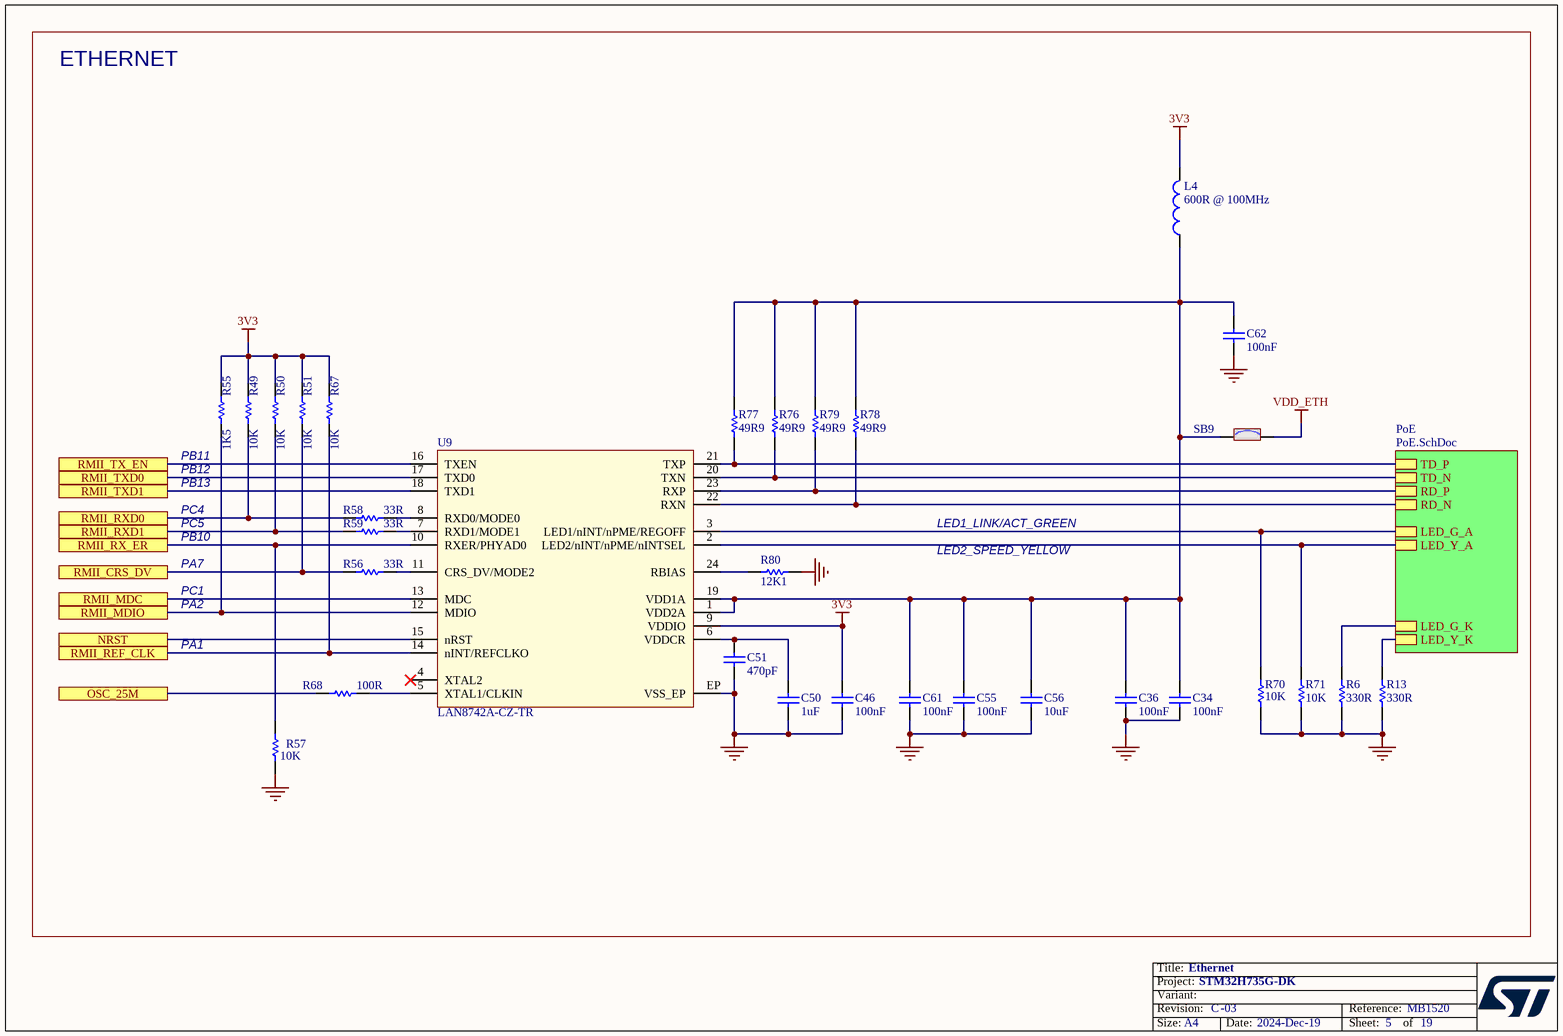
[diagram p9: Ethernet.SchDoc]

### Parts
C34  value 100nF  [C0402]  (hidden comment: Capacitor)
C36  value 100nF  [C0402]  (hidden comment: Capacitor)
C46  value 100nF  [C0402]  (hidden comment: Capacitor)
C50  value 1uF  [C0603]  (hidden comment: Capacitor)
C51  value 470pF  [C0402]  (hidden comment: Capacitor)
C55  value 100nF  [C0402]  (hidden comment: Capacitor)
C56  value 10uF  [C0603]  (hidden comment: Capacitor)
C61  value 100nF  [C0402]  (hidden comment: Capacitor)
C62  value 100nF  [C0402]  (hidden comment: Capacitor)
L4  value 600R @ 100MHz  [L0603]  (hidden comment: BEAD)
R6  value 330R  [R0402]  (hidden comment: Resistor)
R13  value 330R  [R0402]  (hidden comment: Resistor)
R49  value 10K  [R0402]  (hidden comment: Resistor)
R50  value 10K  [R0402]  (hidden comment: Resistor)
R51  value 10K  [R0402]  (hidden comment: Resistor)
R55  value 1K5  [R0402]  (hidden comment: Resistor)
R56  value 33R  [R0402]  (hidden comment: Resistor)
R57  value 10K  [R0402]  (hidden comment: Resistor)
R58  value 33R  [R0402]  (hidden comment: Resistor)
R59  value 33R  [R0402]  (hidden comment: Resistor)
R67  value 10K  [R0402]  (hidden comment: Resistor)
R68  value 100R  [R0402]  (hidden comment: Resistor)
R70  value 10K  [R0402]  (hidden comment: Resistor)
R71  value 10K  [R0402]  (hidden comment: Resistor)
R76  value 49R9  [R0402]  (hidden comment: Resistor)
R77  value 49R9  [R0402]  (hidden comment: Resistor)
R78  value 49R9  [R0402]  (hidden comment: Resistor)
R79  value 49R9  [R0402]  (hidden comment: Resistor)
R80  value 12K1  [R0402]  (hidden comment: Resistor)
SB9  SB_ON  [SOLDER-BRIDGE_R0603-0R]  (value not drawn)
U9  LAN8742A-CZ-TR  [ICC_VQFN24-EPAD_4X4_P050]

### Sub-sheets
PoE = PoE.SchDoc: LED_G_A, LED_G_K, LED_Y_A, LED_Y_K, RD_P, TD_N, TD_P, RD_N

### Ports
NRST, OSC_25M, RMII_CRS_DV, RMII_MDC, RMII_MDIO, RMII_REF_CLK, RMII_RX_ER, RMII_RXD0, RMII_RXD1, RMII_TX_EN, RMII_TXD0, RMII_TXD1

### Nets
3V3: C46.1 L4.2 R49.2 R50.2 R51.1 R55.2 R67.1 U9.9(VDDIO)
GND: C34.2 C36.2 C46.2 C50.1 C51.1 C55.2 C56.1 C61.2 C62.1 R6.1 R13.1 R57.2 R70.2 R71.1 R80.2 U9.EP(VSS_EP)  [project net POE7]
VDD_ETH: SB9.2
OSC_25M: R68.1 ; port OSC_25M
RESET: U9.15(nRST) ; port NRST
RMII_CRS_DV: R51.2 R56.1 ; port RMII_CRS_DV
RMII_MDC: U9.13(MDC) ; port RMII_MDC
RMII_MDIO: R55.1 U9.12(MDIO) ; port RMII_MDIO
RMII_REF_CLK: R67.2 U9.14(nINT/REFCLKO) ; port RMII_REF_CLK
RMII_RX_ER: R57.1 U9.10(RXER/PHYAD0) ; port RMII_RX_ER
RMII_RXD0: R49.1 R58.1 ; port RMII_RXD0
RMII_RXD1: R50.1 R59.1 ; port RMII_RXD1
RMII_TX_EN: U9.16(TXEN) ; port RMII_TX_EN
RMII_TXD0: U9.17(TXD0) ; port RMII_TXD0
RMII_TXD1: U9.18(TXD1) ; port RMII_TXD1
NetC34_1: C34.1 C36.1 C55.1 C56.2 C61.1 C62.2 L4.1 R76.2 R77.2 R78.2 R79.2 SB9.1 U9.1(VDD2A) U9.19(VDD1A)
NetC50_2: C50.2 C51.2 U9.6(VDDCR)
NetR6_2: R6.2 ; sheet PoE/LED_G_K
NetR13_2: R13.2 ; sheet PoE/LED_Y_K
NetR56_2: R56.2 U9.11(CRS_DV/MODE2)
NetR58_2: R58.2 U9.8(RXD0/MODE0)
NetR59_2: R59.2 U9.7(RXD1/MODE1)
NetR68_2: R68.2 U9.5(XTAL1/CLKIN)
NetR70_1: R70.1 U9.3(LED1/nINT/nPME/REGOFF) ; sheet PoE/LED_G_A
NetR71_2: R71.2 U9.2(LED2/nINT/nPME/nINTSEL) ; sheet PoE/LED_Y_A
NetR76_1: R76.1 U9.20(TXN) ; sheet PoE/TD_N
NetR77_1: R77.1 U9.21(TXP) ; sheet PoE/TD_P
NetR78_1: R78.1 U9.22(RXN) ; sheet PoE/RD_N
NetR79_1: R79.1 U9.23(RXP) ; sheet PoE/RD_P
NetR80_1: R80.1 U9.24(RBIAS)

Not connected (* = marked no-connect by the designer): U9 4(XTAL2)*

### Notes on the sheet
- ETHERNET
- PB11
- PB12
- PB13
- PC4
- PA7
- PC5
- PB10
- LED1_LINK/ACT_GREEN
- LED2_SPEED_YELLOW
- PA2
- PC1
- PA1

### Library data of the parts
C34 C36 C46 C55 C61 C62 = MCD-00006: as C32 on sheet STM32_microcontroller_IOs
C50 = MCD-00010: Capacitor, MLCC, 1uF, 16V, X5R, 10%, 0603, T=0,8mm; Manufacturer_Part_Number: CC0603KRX5R7BB105; Manufacturer: YAGEO; Part_Preference: Recommended; Provided_By: SUBCO; Component_Country_Of_Origin: China; ID: 2470; ShowFields: YES
C51 = MCD-00724: Capacitor, MLCC, 470pF, 50V, NPO, 5%, 0402, T=0,5mm; Manufacturer_Part_Number: CC0402JRNPO9BN471; Manufacturer: YAGEO; Part_Preference: Recommended; Provided_By: SUBCO; Component_Country_Of_Origin: China; ID: 3023; Order_Code_RS: 199-2186; ShowFields: YES
C56 = MCD-01124: Capacitor, MLCC, 10uF, 10V, X5R, 10%, 0603, T=0.8mm; Manufacturer_Part_Number: GRM188R61A106KAAL; Manufacturer: MURATA; Part_Preference: Recommended; ECCN_US: EAR99; ECCN_EU: NEC; Provided_By: SUBCO; Component_Country_Of_Origin: Japan; ID: 3372; Order_Code_RS: 170-6258; ShowFields: YES
L4 = MCD-00047: SMD Chip ferrite bead, 600R@100MHz +/-25%, 350mA, 500mohm DC, 0603, T=0.8mm; Part_Type: Inductor; Manufacturer_Part_Number: FCM1608KF-601T03; Manufacturer: TAI-TECH; Part_Preference: Recommended; Partial_Alternate_Internal_Part_Number: MCD-02959; Provided_By: SUBCO; Component_Country_Of_Origin: Unknown; ID: 2546; ShowFields: YES
R6 R13 = MCD-00062: as R141 on sheet STMod+
R49-R51 R57 R67 = MCD-00053: Resistor,10K,0402,1%,1/16W; Manufacturer_Part_Number: RC0402FR-0710KL; Manufacturer: YAGEO; BMS_Part_Number: 9131590; Part_Preference: Recommended; ECCN_US: EAR99; ECCN_EU: NEC; Provided_By: SUBCO; Component_Country_Of_Origin: China; ID: 2539; ShowFields: YES
R55 = MCD-00068: Resistor,1K5,0402,1%,1/16W; Manufacturer_Part_Number: RC0402FR-071K5L; Manufacturer: YAGEO; Part_Preference: Recommended; ECCN_US: EAR99; ECCN_EU: NEC; Provided_By: SUBCO; Component_Country_Of_Origin: China; ID: 2524; ShowFields: YES
R56 R58 R59 = MCD-00455: Resistor,33R,0402,1%,1/16W; Manufacturer_Part_Number: RC0402FR-0733RL; Manufacturer: YAGEO; Part_Preference: Recommended; ECCN_US: EAR99; ECCN_EU: NEC; Provided_By: SUBCO; Component_Country_Of_Origin: China; ID: 2821; ShowFields: YES
R68 = MCD-00067: as R140 on sheet STMod+
R70 R71 = MCD-00053: as R41 on sheet STM32_microcontroller_IOs
R76-R79 = MCD-00565: Resistor,49R9,0402,1%,1/16W; Manufacturer_Part_Number: RC0402FR-0749R9L; Manufacturer: YAGEO; Part_Preference: Recommended; Provided_By: SUBCO; Component_Country_Of_Origin: China; ID: 3178; ShowFields: YES
R80 = MCD-00723: Resistor,12K1,0402,1%,1/16W; Manufacturer_Part_Number: RC0402FR-0712K1L; Manufacturer: YAGEO; Part_Preference: Recommended; ECCN_US: EAR99; ECCN_EU: NEC; Provided_By: SUBCO; Component_Country_Of_Origin: China; ID: 3022; ShowFields: YES
SB9 = MCD-00071: as SB23 on sheet Arduino_Connector
U9 = MCD-00719: 10/100M RMII Ethernet transceiver; Part_Type: IC; Manufacturer: MICROCHIP; BMS_Part_Number: 9177984; Part_Preference: Recommended; Provided_By: SUBCO; Component_Country_Of_Origin: Unknown; ID: 3026; ShowFields: YES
